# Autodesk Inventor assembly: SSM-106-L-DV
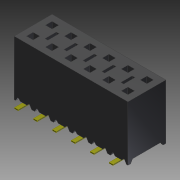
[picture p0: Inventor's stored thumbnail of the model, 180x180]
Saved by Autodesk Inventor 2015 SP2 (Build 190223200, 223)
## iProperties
Category: PARTsolutions
Company: SAMTEC
Created: 2015-08
Part Number: SSM-106-L-DV
Catalog Web Link: www.cadenas.de
Description: SSM Series-SSM Series - (2,54 mm) .100" Tiger Claw™ Surface Mount Socket
Vendor: SAMTEC
Document SubType Name: Assembly
Designer: PARTuser1
Manufacturer: SAMTEC
PSOL_IDENT_0: {$CADENAS_DATA\23d-libs\samtec\modelling\ssm\ssm_asmtab.prj},242 {VTYP=3D},{STYP=ASSTAB},{NB=SSM-106
PSOL_IDENT_1: -L-DV},{LINA=SSM-106-L-DV},{NN=SSM Series},{DATE=15.05.2015 12:28:12},{GEOMDATE=24.10.2014 06:52:24}
PSOL_IDENT_2: ,{VERSION=},{LINEID=10},{LINESUBID=-1},{WBVAR=POS,ROW,PLOPT,BEOPT,LCOPT,POLOPT,AOPT,POPT,MOPT,KOPT,T
PSOL_IDENT_3: ROPT}  {NB=SSM-106-L-DV},{LINA=SSM-106-L-DV},{KT=DUMMY},{PN=SSM-106-L-DV},{SERIES=SSM},{POS=6},{POSP
PSOL_IDENT_4: N=06},{ROW=-DV},{ROWALG= '-SV','-SV - Single Vertical','-SH','-SH - Single Horizontal','-DH','-DH -
PSOL_IDENT_5: Double Horizontal','-DV','-DV - Double Vertical' },{PLOPT=-L},{PLOPTALG= '-S','-S - 30micro\" Select
PSOL_IDENT_6: ive Gold in Contact Area, Matte Tin on Tail','-L','-L - 10micro\" Light Selective Gold in Contact Ar
PSOL_IDENT_7: ea, Matte Tin on Tail','-T','-T - Matte Tin Contact and Tail (Non-standard option -  Please contact
PSOL_IDENT_8: SAMTEC)','-F','-F - 3micro\" Flash Selective Gold Contact, Matte Tin on Tail','-H','-H - 30micro\" H
PSOL_IDENT_9: eavy Gold in Contact Area, 3micro\" on Tail (Non-standard option -  Please contact SAMTEC)','-STL','
PSOL_IDENT_10: -STL - 30micro\" Selective Gold in Contact Area, Tin/Lead (90/10+/-5%) Tail (Non-standard option -
PSOL_IDENT_11: Please contact SAMTEC)','-SM','-SM - 30micro\" Selective Gold in Contact Area, Matte Tin on Tail (No
PSOL_IDENT_12: n-standard option -  Please contact SAMTEC)','-LM','-LM - 10micro\" Light Selective Gold in Contact
PSOL_IDENT_13: Area, Matte Tin Tail (Non-standard option -  Please contact SAMTEC)','-TM','-TM - Matte Tin Contact
PSOL_IDENT_14: and tail (Non-standard option -  Please contact SAMTEC)','-FM','-FM - 3micro\" Flash Selective Gold
PSOL_IDENT_15: in Contact Area, Matte Tin Tail (Non-standard option -  Please contact SAMTEC)' },{BEOPT=},{BEOPTALG=
PSOL_IDENT_16: '','Not Selected','-BE','-BE - Bottom Entry' },{LCOPT=},{LCOPTALG= '','Not Selected','-LC','-LC Loc
PSOL_IDENT_17: king Clip' },{POLOPT=},{POLOPTALG= '','Not Selected','001','001','002','002','003','003','004','004'
PSOL_IDENT_18: ,'005','005','006','006','007','007','008','008','009','009','010','010','011','011','012','012' },{
PSOL_IDENT_19: POLOPTMAX=144},{POLOPTMAX2='001','001','002','002','003','003','004','004','005','005','006','006','
PSOL_IDENT_20: 007','007','008','008','009','009','010','010','011','011','012','012'},{POLOPTPN=},{POLARIZE='001','
PSOL_IDENT_21: 001','002','002','003','003','004','004','005','005','006','006','007','007','008','008','009','009'
PSOL_IDENT_22: ,'010','010','011','011','012','012','013','013','014','014','015','015','016','016','017','017','01
PSOL_IDENT_23: 8','018','019','019','020','020','021','021','022','022','023','023','024','024','025','025','026','
PSOL_IDENT_24: 026','027','027','028','028','029','029','030','030','031','031','032','032','033','033','034','034'
PSOL_IDENT_25: ,'035','035','036','036','037','037','038','038','039','039','040','040','041','041','042','042','04
PSOL_IDENT_26: 3','043','044','044','045','045','046','046','047','047','048','048','049','049','050','050','051','
PSOL_IDENT_27: 051','052','052','053','053','054','054','055','055','056','056','057','057','058','058','059','059'
PSOL_IDENT_28: ,'060','060','061','061','062','062','063','063','064','064','065','065','066','066','067','067','06
PSOL_IDENT_29: 8','068','069','069','070','070','071','071','072','072','073','073','074','074','075','075','076','
PSOL_IDENT_30: 076','077','077','078','078','079','079','080','080'},{AOPT=},{AOPTALG= '','Not Selected','-A','-A -
PSOL_IDENT_31: Alignment Pin (Non-standard option -  Please contact SAMTEC)' },{POPT=},{POPTALG= '','Not Selected'
PSOL_IDENT_32: ,'-P','-P - Pick & Place Pad' },{MOPT=},{MOPTALG= '','Not Selected','-M','-M - Metal Pick & Place Pa
PSOL_IDENT_33: d' },{KOPT=},{KOPTALG= '','Not Selected','-K','-K - Polyimide Film Pad' },{TROPT=},{TROPALG= '','Not
PSOL_IDENT_34: Selected','-TR','-TR - Tape & Reel'  },{PPATH=parts/ssm_asmtpl.prj}
NN: SSM Series
NT: SSM Series - (2,54 mm) .100" Tiger Claw™ Surface Mount Socket
NB: SSM-106-L-DV
NBSYN: $PN.
LINA: SSM-106-L-DV
PN: SSM-106-L-DV
SERIES: SSM
POS: 6
ROW: -DV - Double Vertical
PLOPT: -L - 10micro" Light Selective Gold in Contact Area, Matte Tin on Tail
BEOPT: Not Selected
LCOPT: Not Selected
POLOPT: Not Selected
AOPT: Not Selected
POPT: Not Selected
MOPT: Not Selected
KOPT: Not Selected
TROPT: Not Selected
SUPPLIER: SAMTEC
ARTICLENO: SSM-106-L-DV
BOMINFO: SSM-106-L-DV
CREATOR: CADENAS GmbH
Title: SSM-106-L-DV
Author: Cadenas PARTsolutions
Comments: SSM Series - (2,54 mm) .100" Tiger Claw™ Surface Mount Socket
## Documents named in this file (3)
- E:\Tigers SVN\mechanik\2016\Inventor\Kaufteile\SSM-106-L-DV\SSM-106-L-DV.iam
- E:\Tigers SVN\mechanik\2016\Inventor\Kaufteile\SSM-106-L-DV\SSM-106-L-DV_body.ipt
- E:\Tigers SVN\mechanik\2016\Inventor\Kaufteile\SSM-106-L-DV\C-137-016.ipt
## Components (2 placed, 2 different names)
1. SSM-106-L-DV_body:1
2. C-137-016:1
